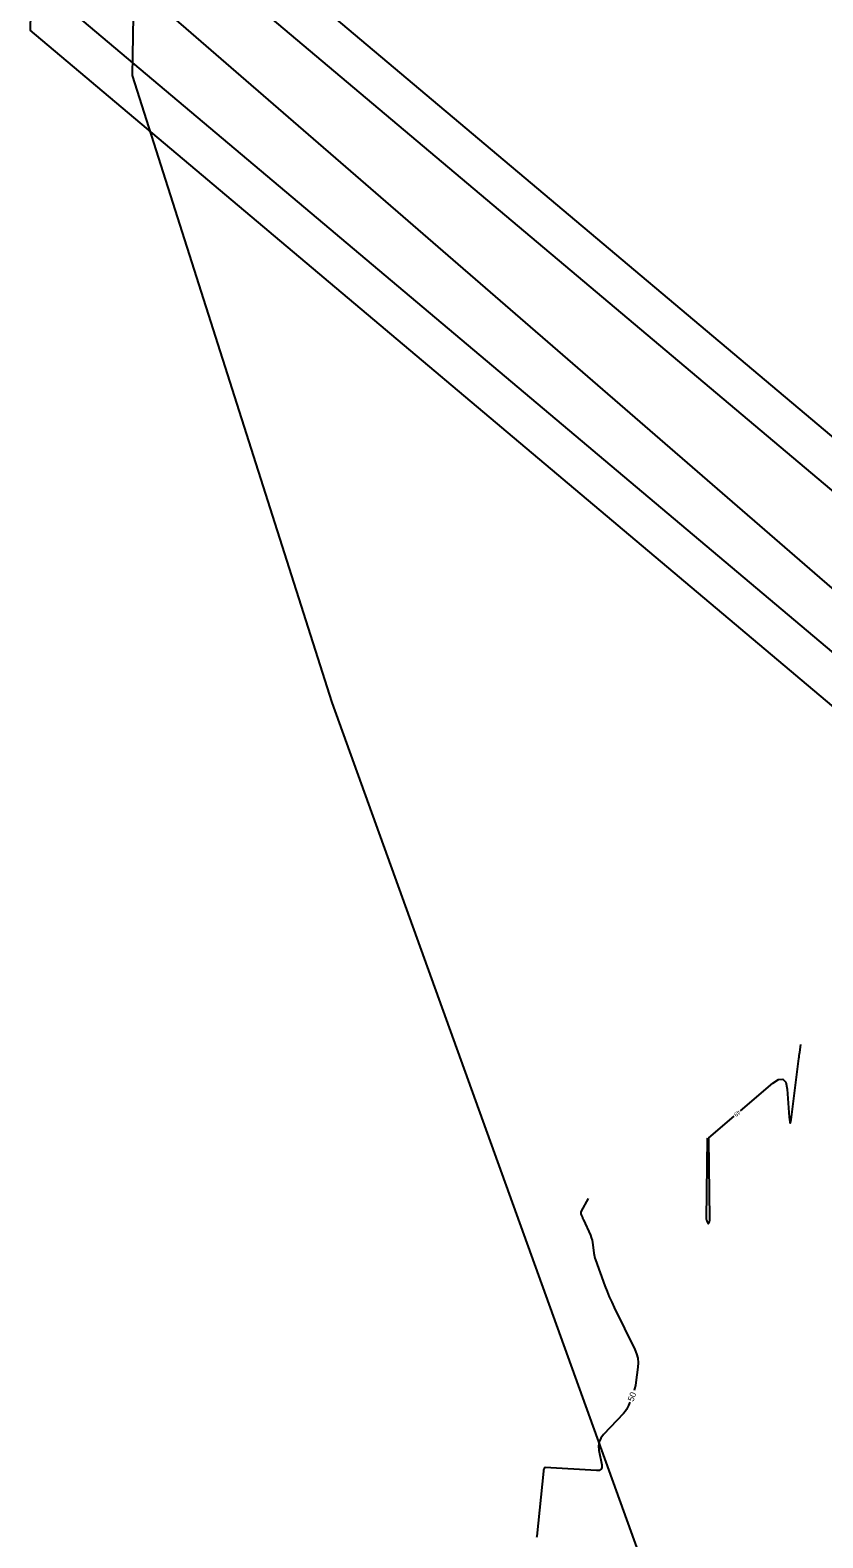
# Model space of a CAD drawing. Extents: x 2384780 to 2405861, y 547869 to 573706.
# Drawn here: x 2391351 to 2391736, y 553366 to 554098 of the extents above; entities that cross this region are included whole.
import ezdxf

# ---------------------------------------------------------------- set-up
doc = ezdxf.new("R2010")
doc.units = 0
for name, color, linetype in [('Old_Level_10', 7, 'Continuous'), ('Old_Level_60', 7, 'Continuous'), ('Old_Level_61', 7, 'Continuous'), ('Prop Buffer Zone 1', 7, 'Continuous'), ('Prop Buffer Zone 2', 7, 'Continuous')]:
    doc.layers.add(name, color=color, linetype=linetype)

msp = doc.modelspace()

# ---------------------------------------------------------------- linework, layer by layer
at = {"layer": 'Old_Level_10'}
for p, q in [((2391400.967, 554120.885), (2391400.252, 554075.909)), ((2391860.4825, 553722.89325), (2391400.967, 554120.885)), ((2391400.252, 554075.909), (2391497.285, 553771.369)), ((2391497.285, 553771.369), (2391720.4865, 553152.56075))]:
    msp.add_line(p, q, dxfattribs=at)
at = {"layer": 'Old_Level_60'}
for points in [[(2391695.832, 553573.10375), (2391711.4805, 553586.50475), (2391714.302, 553588.36475), (2391716.40975, 553588.5015), (2391717.80375, 553586.91475), (2391718.484, 553583.6045), (2391719.54025, 553569.976), (2391719.7825, 553567.784), (2391720.05725, 553567.04925), (2391720.36375, 553567.77125), (2391720.7025, 553569.95025), (2391724.1855, 553598.4905), (2391724.28325, 553599.2715), (2391724.3855, 553600.052), (2391724.49225, 553600.83175), (2391724.6035, 553601.611), (2391725.134, 553605.24575)], [(2391679.7105, 553559.853), (2391679.67525, 553559.789), (2391679.6685, 553559.77475), (2391679.66375, 553559.7605), (2391679.66075, 553559.7455), (2391679.65975, 553559.73), (2391679.2285, 553520.3895), (2391679.23175, 553520.2915), (2391679.244, 553520.19525), (2391679.26475, 553520.1005), (2391679.2945, 553520.00725), (2391679.406, 553519.705), (2391679.4305, 553519.64075), (2391679.457, 553519.577), (2391679.485, 553519.514), (2391679.5145, 553519.45175), (2391680.013, 553518.43875), (2391680.1045, 553518.3), (2391680.1975, 553518.25275), (2391680.2925, 553518.2965), (2391680.389, 553518.43175), (2391680.839, 553519.26625), (2391680.84125, 553519.27075), (2391680.843, 553519.2755), (2391680.844, 553519.28025), (2391680.84475, 553519.28525), (2391680.84625, 553519.30175), (2391680.8465, 553519.30525), (2391680.84675, 553519.309), (2391680.84725, 553519.3125), (2391680.8475, 553519.316), (2391680.90025, 553519.92225), (2391680.91, 553520.05225), (2391680.9165, 553520.1825), (2391680.9195, 553520.31275), (2391680.9195, 553520.443), (2391680.41025, 553559.3945), (2391680.41025, 553559.45675), (2391680.41225, 553559.519), (2391680.416, 553559.581), (2391680.4215, 553559.643), (2391680.44275, 553559.8455), (2391680.451, 553559.88725), (2391680.46625, 553559.925), (2391680.4885, 553559.959), (2391680.51825, 553559.98925), (2391692.79375, 553570.50175)]]:
    msp.add_lwpolyline(points, dxfattribs=at)
at = {"layer": 'Old_Level_61'}
for points in [[(2391621.83075, 553530.4765), (2391618.42875, 553524.297), (2391618.25625, 553523.8875), (2391618.18775, 553523.474), (2391618.22275, 553523.05625), (2391618.3615, 553522.6345), (2391618.984, 553521.2495), (2391619.1175, 553520.9525), (2391619.25075, 553520.65575), (2391619.38425, 553520.359), (2391619.5175, 553520.06225), (2391622.8675, 553512.609), (2391623.323, 553511.47925), (2391623.68475, 553510.324), (2391623.953, 553509.14375), (2391624.128, 553507.938), (2391624.54625, 553503.9585), (2391624.66175, 553503.112), (2391624.829, 553502.27725), (2391625.048, 553501.45475), (2391625.31875, 553500.644), (2391629.9585, 553488.05925), (2391630.98725, 553485.37725), (2391632.08425, 553482.7245), (2391633.25, 553480.10125), (2391634.4845, 553477.5075), (2391644.5165, 553457.11375), (2391645.35825, 553455.0465), (2391645.8765, 553452.92575), (2391646.071, 553450.751), (2391645.94175, 553448.52275), (2391644.99075, 553441.15575), (2391644.73975, 553439.58925), (2391644.39475, 553438.04675), (2391644.143, 553437.17775)], [(2391642.0575, 553431.55475), (2391641.441, 553429.982), (2391640.9695, 553428.9295), (2391640.40375, 553427.937), (2391639.7435, 553427.0045), (2391638.989, 553426.132), (2391629.193, 553415.838), (2391627.91175, 553414.1645), (2391627.1175, 553412.34875), (2391626.81025, 553410.39075), (2391626.9905, 553408.2905), (2391628.3745, 553401.198), (2391628.44075, 553399.8795), (2391628.04625, 553398.96375), (2391627.1915, 553398.45075), (2391625.876, 553398.34075), (2391600.9735, 553399.811), (2391600.76775, 553399.79575), (2391600.60125, 553399.72325), (2391600.474, 553399.594), (2391600.38575, 553399.4075), (2391600.162, 553398.705), (2391600.118, 553398.55375), (2391600.08225, 553398.40075), (2391600.0545, 553398.246), (2391600.03475, 553398.08975), (2391596.8835, 553366.43475), (2391596.75925, 553365.879)]]:
    msp.add_lwpolyline(points, dxfattribs=at)
at = {"layer": 'Prop Buffer Zone 1'}
for p, q in [((2391883.60825, 553753.75325), (2391434.222, 554132.1035)), ((2391844.10775, 553708.5765), (2391370.7443, 554107.11367))]:
    msp.add_line(p, q, dxfattribs=at)
at = {"layer": 'Prop Buffer Zone 2'}
for p, q in [((2391896.48925, 553769.05275), (2391456.39225, 554139.58225)), ((2391351.05475, 554126.807), (2391350.59573, 554097.93289)), ((2391833.93475, 553690.99675), (2391350.59573, 554097.93289))]:
    msp.add_line(p, q, dxfattribs=at)

# ---------------------------------------------------------------- texts
at = {"layer": 'Old_Level_60'}
msp.add_text('49', height=2, rotation=220.57601111, dxfattribs=at).set_placement((2391694.78675, 553573.525))
at = {"layer": 'Old_Level_61'}
msp.add_text('50', height=3, rotation=69.65028333, dxfattribs=at).set_placement((2391643.73725, 553431.6115))

doc.saveas('drawing.dxf')
